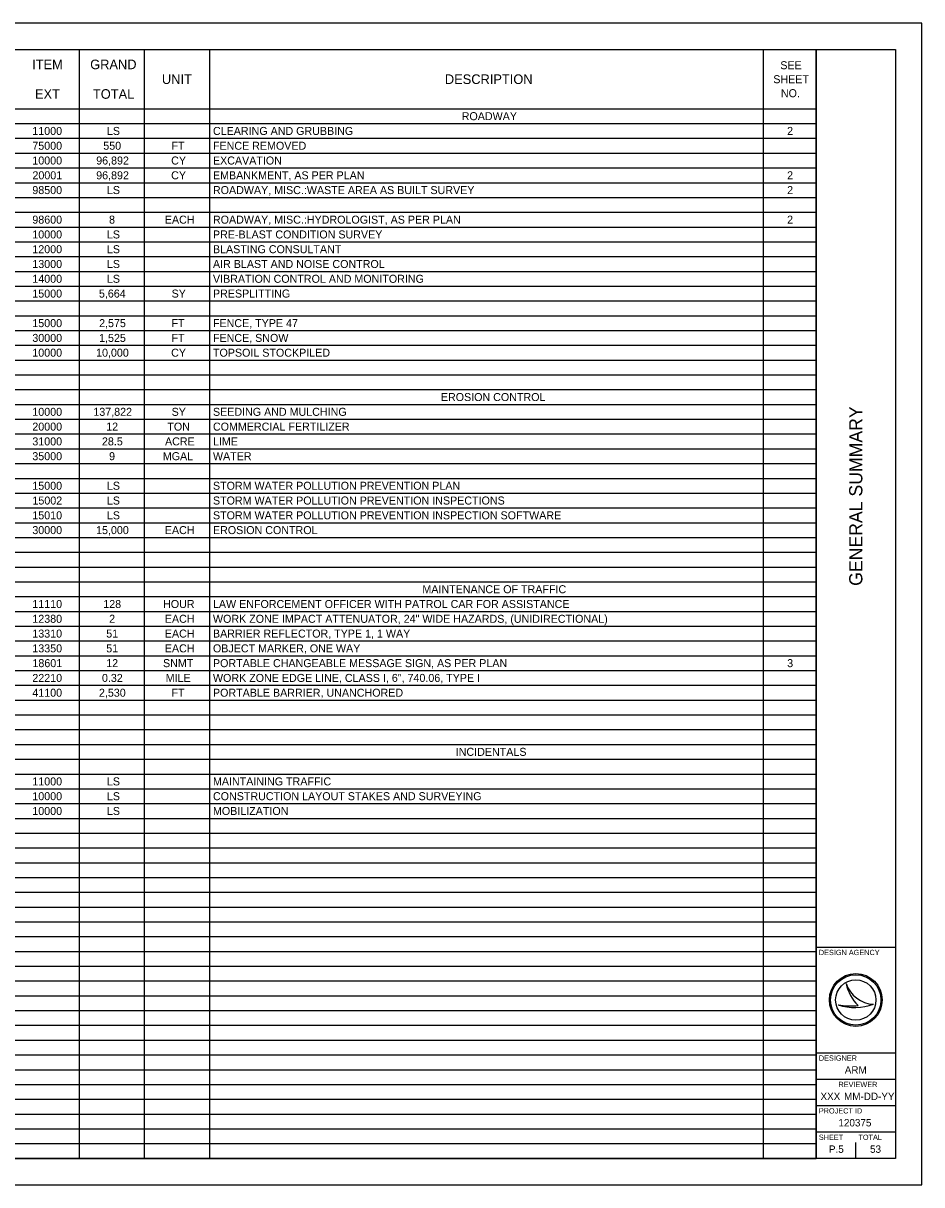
# Model space of a CAD drawing. Extents: x 0 to 34, y 0 to 22.
# Drawn here: x 16.98 to 34, y 0 to 22 of the extents above; entities that cross this region are included whole.
import ezdxf

# ---------------------------------------------------------------- set-up
doc = ezdxf.new("R2010")
doc.units = 0
for name, color, linetype in [('SH_Border', 7, 'Continuous'), ('SH_Cut_Line', 7, 'Continuous'), ('SH_Data', 7, 'Continuous'), ('SH_Text', 7, 'Continuous')]:
    doc.layers.add(name, color=color, linetype=linetype)

msp = doc.modelspace()

# ---------------------------------------------------------------- linework, layer by layer
at = {"layer": 'SH_Border'}
for p, q in [((32, 0.5), (32, 21.5)), ((32, 4.5), (33.5, 4.5)), ((32, 2.5), (33.5, 2.5)), ((32, 2), (33.5, 2)), ((32, 1.5), (33.5, 1.5)), ((32, 1), (33.5, 1))]:
    msp.add_line(p, q, dxfattribs=at)
msp.add_lwpolyline([(1.5, 21.5), (33.5, 21.5), (33.5, 0.5), (1.5, 0.5)], close=True, dxfattribs=at)
at = {"layer": 'SH_Cut_Line'}
msp.add_lwpolyline([(0, 0), (34, 0), (34, 22), (0, 22)], close=True, dxfattribs=at)
at = {"layer": 'SH_Data'}
for p, q in [((32.567, 3.81), (32.567, 3.81)), ((32.417, 3.41), (32.417, 3.41)), ((32.75, 3.5), (32.75, 3.5)), ((33.087, 3.419), (33.087, 3.419)), ((32.375, 0.675), (32.375, 0.675)), ((32.75, 0.5), (32.75, 0.8))]:
    msp.add_line(p, q, dxfattribs=at)
for radius in [0.5, 0.477, 0.477, 0.382]:
    msp.add_circle((32.75, 3.5), radius, dxfattribs=at)
for centre, radius, start, end in [((33.116, 3.998), 0.58, 198.9257, 198.9319), ((33.347, 3.97), 0.796, 191.6379, 191.6421), ((33.116, 3.998), 0.58, 198.9319, 267.1657), ((33.347, 3.97), 0.796, 191.6421, 226.0947), ((32.739, 4.37), 1.013, 251.4576, 290.0832), ((32.648, 4.654), 1.266, 259.4964, 259.4995), ((32.739, 4.37), 1.013, 251.4527, 251.4576), ((32.648, 4.654), 1.266, 259.4995, 276.6672)]:
    msp.add_arc(centre, radius, start, end, dxfattribs=at)
at = {"layer": 'SH_Text'}
for p, q in [((1.5, 21.5), (32, 21.5)), ((18.035, 21.5), (18.035, 0.5)), ((19.27, 21.5), (19.27, 0.5)), ((20.505, 21.5), (20.505, 0.5)), ((30.995, 21.5), (30.995, 0.5)), ((32, 21.5), (32, 0.5)), ((1.5, 20.38), (32, 20.38)), ((1.5, 20.1), (32, 20.1)), ((1.5, 19.82), (32, 19.82)), ((1.5, 19.54), (32, 19.54)), ((1.5, 19.26), (32, 19.26)), ((1.5, 18.98), (32, 18.98)), ((1.5, 18.7), (32, 18.7)), ((1.5, 18.42), (32, 18.42)), ((1.5, 18.14), (32, 18.14)), ((1.5, 17.86), (32, 17.86)), ((1.5, 17.58), (32, 17.58)), ((1.5, 17.3), (32, 17.3)), ((1.5, 17.02), (32, 17.02)), ((1.5, 16.74), (32, 16.74)), ((1.5, 16.46), (32, 16.46)), ((1.5, 16.18), (32, 16.18)), ((1.5, 15.9), (32, 15.9)), ((1.5, 15.62), (32, 15.62)), ((1.5, 15.34), (32, 15.34)), ((1.5, 15.06), (32, 15.06)), ((1.5, 14.78), (32, 14.78)), ((1.5, 14.5), (32, 14.5)), ((1.5, 14.22), (32, 14.22)), ((1.5, 13.94), (32, 13.94)), ((1.5, 13.66), (32, 13.66)), ((1.5, 13.38), (32, 13.38)), ((1.5, 13.1), (32, 13.1)), ((1.5, 12.82), (32, 12.82)), ((1.5, 12.54), (32, 12.54)), ((1.5, 12.26), (32, 12.26)), ((1.5, 11.98), (32, 11.98)), ((1.5, 11.7), (32, 11.7)), ((1.5, 11.42), (32, 11.42)), ((1.5, 11.14), (32, 11.14)), ((1.5, 10.86), (32, 10.86)), ((1.5, 10.58), (32, 10.58)), ((1.5, 10.3), (32, 10.3)), ((1.5, 10.02), (32, 10.02)), ((1.5, 9.74), (32, 9.74)), ((1.5, 9.46), (32, 9.46)), ((1.5, 9.18), (32, 9.18)), ((1.5, 8.9), (32, 8.9)), ((1.5, 8.62), (32, 8.62)), ((1.5, 8.34), (32, 8.34)), ((1.5, 8.06), (32, 8.06)), ((1.5, 7.78), (32, 7.78)), ((1.5, 7.5), (32, 7.5)), ((1.5, 7.22), (32, 7.22)), ((1.5, 6.94), (32, 6.94)), ((1.5, 6.66), (32, 6.66)), ((1.5, 6.38), (32, 6.38)), ((1.5, 6.1), (32, 6.1)), ((1.5, 5.82), (32, 5.82)), ((1.5, 5.54), (32, 5.54)), ((1.5, 5.26), (32, 5.26)), ((1.5, 4.98), (32, 4.98)), ((1.5, 4.7), (32, 4.7)), ((1.5, 4.42), (32, 4.42)), ((1.5, 4.14), (32, 4.14)), ((1.5, 3.86), (32, 3.86)), ((1.5, 3.58), (32, 3.58)), ((1.5, 3.3), (32, 3.3)), ((1.5, 3.02), (32, 3.02)), ((1.5, 2.74), (32, 2.74)), ((1.5, 2.46), (32, 2.46)), ((1.5, 2.18), (32, 2.18)), ((1.5, 1.9), (32, 1.9)), ((1.5, 1.62), (32, 1.62)), ((1.5, 1.34), (32, 1.34)), ((1.5, 1.06), (32, 1.06)), ((1.5, 0.78), (32, 0.78)), ((1.5, 0.5), (32, 0.5))]:
    msp.add_line(p, q, dxfattribs=at)

# ---------------------------------------------------------------- texts
at = {"layer": 'SH_Data'}
msp.add_text('GENERAL SUMMARY', height=0.25, rotation=90, dxfattribs=at).set_placement((32.875, 11.344))
for s, height, p in [('DESIGN AGENCY', 0.1, (32.05, 4.35)), ('DESIGNER', 0.1, (32.05, 2.35)), ('ARM', 0.14, (32.541, 2.105)), ('REVIEWER', 0.1, (32.422, 1.85)), ('XXX', 0.14, (32.081, 1.605)), ('MM-DD-YY', 0.14, (32.527, 1.605)), ('PROJECT ID', 0.1, (32.05, 1.35)), ('120375', 0.14, (32.421, 1.105)), ('SHEET', 0.1, (32.05, 0.85)), ('TOTAL', 0.1, (32.8, 0.85)), ('P.5', 0.14, (32.241, 0.605)), ('53', 0.14, (33.02, 0.605))]:
    msp.add_text(s, height=height, dxfattribs=at).set_placement(p)
at = {"layer": 'SH_Text'}
for s, height, p in [('ITEM', 0.1818, (17.145, 21.129)), ('GRAND', 0.1818, (18.245, 21.129)), ('SEE ', 0.1515, (31.32, 21.129)), ('UNIT', 0.1818, (19.604, 20.849)), ('DESCRIPTION', 0.18184, (24.965, 20.849)), ('SHEET ', 0.1515, (31.187, 20.864)), ('EXT', 0.1818, (17.199, 20.569)), ('TOTAL', 0.1818, (18.297, 20.569)), ('NO.', 0.1515, (31.331, 20.599)), ('ROADWAY', 0.1515, (25.284, 20.164)), ('11000', 0.1515, (17.149, 19.884)), ('LS', 0.1515, (18.562, 19.884)), ('CLEARING AND GRUBBING', 0.15153, (20.571, 19.884)), ('2', 0.152, (31.449, 19.884)), ('75000', 0.1515, (17.149, 19.604)), ('550', 0.1515, (18.493, 19.604)), ('FT', 0.1515, (19.786, 19.604)), ('FENCE REMOVED', 0.15153, (20.571, 19.604)), ('10000', 0.1515, (17.149, 19.324)), ('96,892', 0.1515, (18.359, 19.324)), ('CY', 0.1515, (19.779, 19.324)), ('EXCAVATION', 0.1515, (20.571, 19.324)), ('20001', 0.1515, (17.151, 19.044)), ('96,892', 0.1515, (18.359, 19.044)), ('CY', 0.1515, (19.779, 19.044)), ('EMBANKMENT, AS PER PLAN', 0.15153, (20.571, 19.044)), ('2', 0.152, (31.449, 19.044)), ('98500', 0.1515, (17.149, 18.764)), ('LS', 0.1515, (18.562, 18.764)), ('ROADWAY, MISC.:WASTE AREA AS BUILT SURVEY', 0.15153, (20.571, 18.764)), ('2', 0.152, (31.449, 18.764)), ('98600', 0.1515, (17.149, 18.204)), ('8', 0.152, (18.602, 18.204)), ('EACH', 0.1515, (19.659, 18.204)), ('ROADWAY, MISC.:HYDROLOGIST, AS PER PLAN', 0.15153, (20.571, 18.204)), ('2', 0.152, (31.449, 18.204)), ('10000', 0.1515, (17.149, 17.924)), ('LS', 0.1515, (18.562, 17.924)), ('PRE-BLAST CONDITION SURVEY', 0.15153, (20.571, 17.924)), ('12000', 0.1515, (17.149, 17.644)), ('LS', 0.1515, (18.562, 17.644)), ('BLASTING CONSULTANT', 0.15153, (20.571, 17.644)), ('13000', 0.1515, (17.149, 17.364)), ('LS', 0.1515, (18.562, 17.364)), ('AIR BLAST AND NOISE CONTROL', 0.15153, (20.571, 17.364)), ('14000', 0.1515, (17.149, 17.084)), ('LS', 0.1515, (18.562, 17.084)), ('VIBRATION CONTROL AND MONITORING', 0.15153, (20.571, 17.084)), ('15000', 0.1515, (17.149, 16.804)), ('5,664', 0.1515, (18.411, 16.804)), ('SY', 0.1515, (19.788, 16.804)), ('PRESPLITTING', 0.15153, (20.571, 16.804)), ('15000', 0.1515, (17.149, 16.244)), ('2,575', 0.1515, (18.414, 16.244)), ('FT', 0.1515, (19.786, 16.244)), ('FENCE, TYPE 47', 0.15153, (20.571, 16.244)), ('30000', 0.1515, (17.149, 15.964)), ('1,525', 0.1515, (18.414, 15.964)), ('FT', 0.1515, (19.786, 15.964)), ('FENCE, SNOW', 0.15153, (20.571, 15.964)), ('10000', 0.1515, (17.149, 15.684)), ('10,000', 0.1515, (18.357, 15.684)), ('CY', 0.1515, (19.779, 15.684)), ('TOPSOIL STOCKPILED', 0.15153, (20.571, 15.684)), ('EROSION CONTROL', 0.15153, (24.889, 14.844)), ('10000', 0.1515, (17.149, 14.564)), ('137,822', 0.1515, (18.305, 14.564)), ('SY', 0.1515, (19.788, 14.564)), ('SEEDING AND MULCHING', 0.15153, (20.571, 14.564)), ('20000', 0.1515, (17.149, 14.284)), ('12', 0.1515, (18.549, 14.284)), ('TON', 0.1515, (19.707, 14.284)), ('COMMERCIAL FERTILIZER', 0.15153, (20.571, 14.284)), ('31000', 0.1515, (17.149, 14.004)), ('28.5', 0.1515, (18.468, 14.004)), ('ACRE', 0.1515, (19.663, 14.004)), ('LIME', 0.1515, (20.571, 14.004)), ('35000', 0.1515, (17.149, 13.724)), ('9', 0.152, (18.603, 13.724)), ('MGAL', 0.1515, (19.621, 13.724)), ('WATER', 0.1515, (20.571, 13.724)), ('15000', 0.1515, (17.149, 13.164)), ('LS', 0.1515, (18.562, 13.164)), ('STORM WATER POLLUTION PREVENTION PLAN', 0.15153, (20.571, 13.164)), ('15002', 0.1515, (17.151, 12.884)), ('LS', 0.1515, (18.562, 12.884)), ('STORM WATER POLLUTION PREVENTION INSPECTIONS', 0.15153, (20.571, 12.884)), ('15010', 0.1515, (17.149, 12.604)), ('LS', 0.1515, (18.562, 12.604)), ('STORM WATER POLLUTION PREVENTION INSPECTION SOFTWARE', 0.15153, (20.571, 12.604)), ('30000', 0.1515, (17.149, 12.324)), ('15,000', 0.1515, (18.357, 12.324)), ('EACH', 0.1515, (19.659, 12.324)), ('EROSION CONTROL', 0.15153, (20.571, 12.324)), ('MAINTENANCE OF TRAFFIC', 0.15153, (24.539, 11.204)), ('11110', 0.1515, (17.149, 10.924)), ('128', 0.1515, (18.493, 10.924)), ('HOUR', 0.1515, (19.626, 10.924)), ('LAW ENFORCEMENT OFFICER WITH PATROL CAR FOR ASSISTANCE', 0.15153, (20.571, 10.924)), ('12380', 0.1515, (17.149, 10.644)), ('2', 0.152, (18.604, 10.644)), ('EACH', 0.1515, (19.659, 10.644)), ('WORK ZONE IMPACT ATTENUATOR, 24" WIDE HAZARDS, (UNIDIRECTIONAL)', 0.15153, (20.571, 10.644)), ('13310', 0.1515, (17.149, 10.364)), ('51', 0.1515, (18.549, 10.364)), ('EACH', 0.1515, (19.659, 10.364)), ('BARRIER REFLECTOR, TYPE 1, 1 WAY', 0.15153, (20.571, 10.364)), ('13350', 0.1515, (17.149, 10.084)), ('51', 0.1515, (18.549, 10.084)), ('EACH', 0.1515, (19.659, 10.084)), ('OBJECT MARKER, ONE WAY', 0.15153, (20.571, 10.084)), ('18601', 0.1515, (17.151, 9.804)), ('12', 0.1515, (18.549, 9.804)), ('SNMT', 0.1515, (19.625, 9.804)), ('PORTABLE CHANGEABLE MESSAGE SIGN, AS PER PLAN', 0.15153, (20.571, 9.804)), ('3', 0.152, (31.45, 9.804)), ('22210', 0.1515, (17.149, 9.524)), ('0.32', 0.1515, (18.468, 9.524)), ('MILE', 0.1515, (19.676, 9.524)), ('WORK ZONE EDGE LINE, CLASS I, 6", 740.06, TYPE I', 0.15153, (20.571, 9.524)), ('41100', 0.1515, (17.149, 9.244)), ('2,530', 0.1515, (18.411, 9.244)), ('FT', 0.1515, (19.786, 9.244)), ('PORTABLE BARRIER, UNANCHORED', 0.15153, (20.571, 9.244)), ('INCIDENTALS', 0.15153, (25.171, 8.124)), ('11000', 0.1515, (17.149, 7.564)), ('LS', 0.1515, (18.562, 7.564)), ('MAINTAINING TRAFFIC', 0.15153, (20.571, 7.564)), ('10000', 0.1515, (17.149, 7.284)), ('LS', 0.1515, (18.562, 7.284)), ('CONSTRUCTION LAYOUT STAKES AND SURVEYING', 0.15153, (20.571, 7.284)), ('10000', 0.1515, (17.149, 7.004)), ('LS', 0.1515, (18.562, 7.004)), ('MOBILIZATION', 0.15153, (20.571, 7.004))]:
    msp.add_text(s, height=height, dxfattribs=at).set_placement(p)

doc.saveas('drawing.dxf')
